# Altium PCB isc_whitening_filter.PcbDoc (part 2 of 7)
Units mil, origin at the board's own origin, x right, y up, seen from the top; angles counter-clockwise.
Board outline 8440 x 7000 mil, 6 copper layers (Top Layer, MidLayer1, InternalPlane1, Internal Plane 3, InternalPlane2, Bottom Layer); 550 components, 434 nets, 2189 pads, 806 vias.
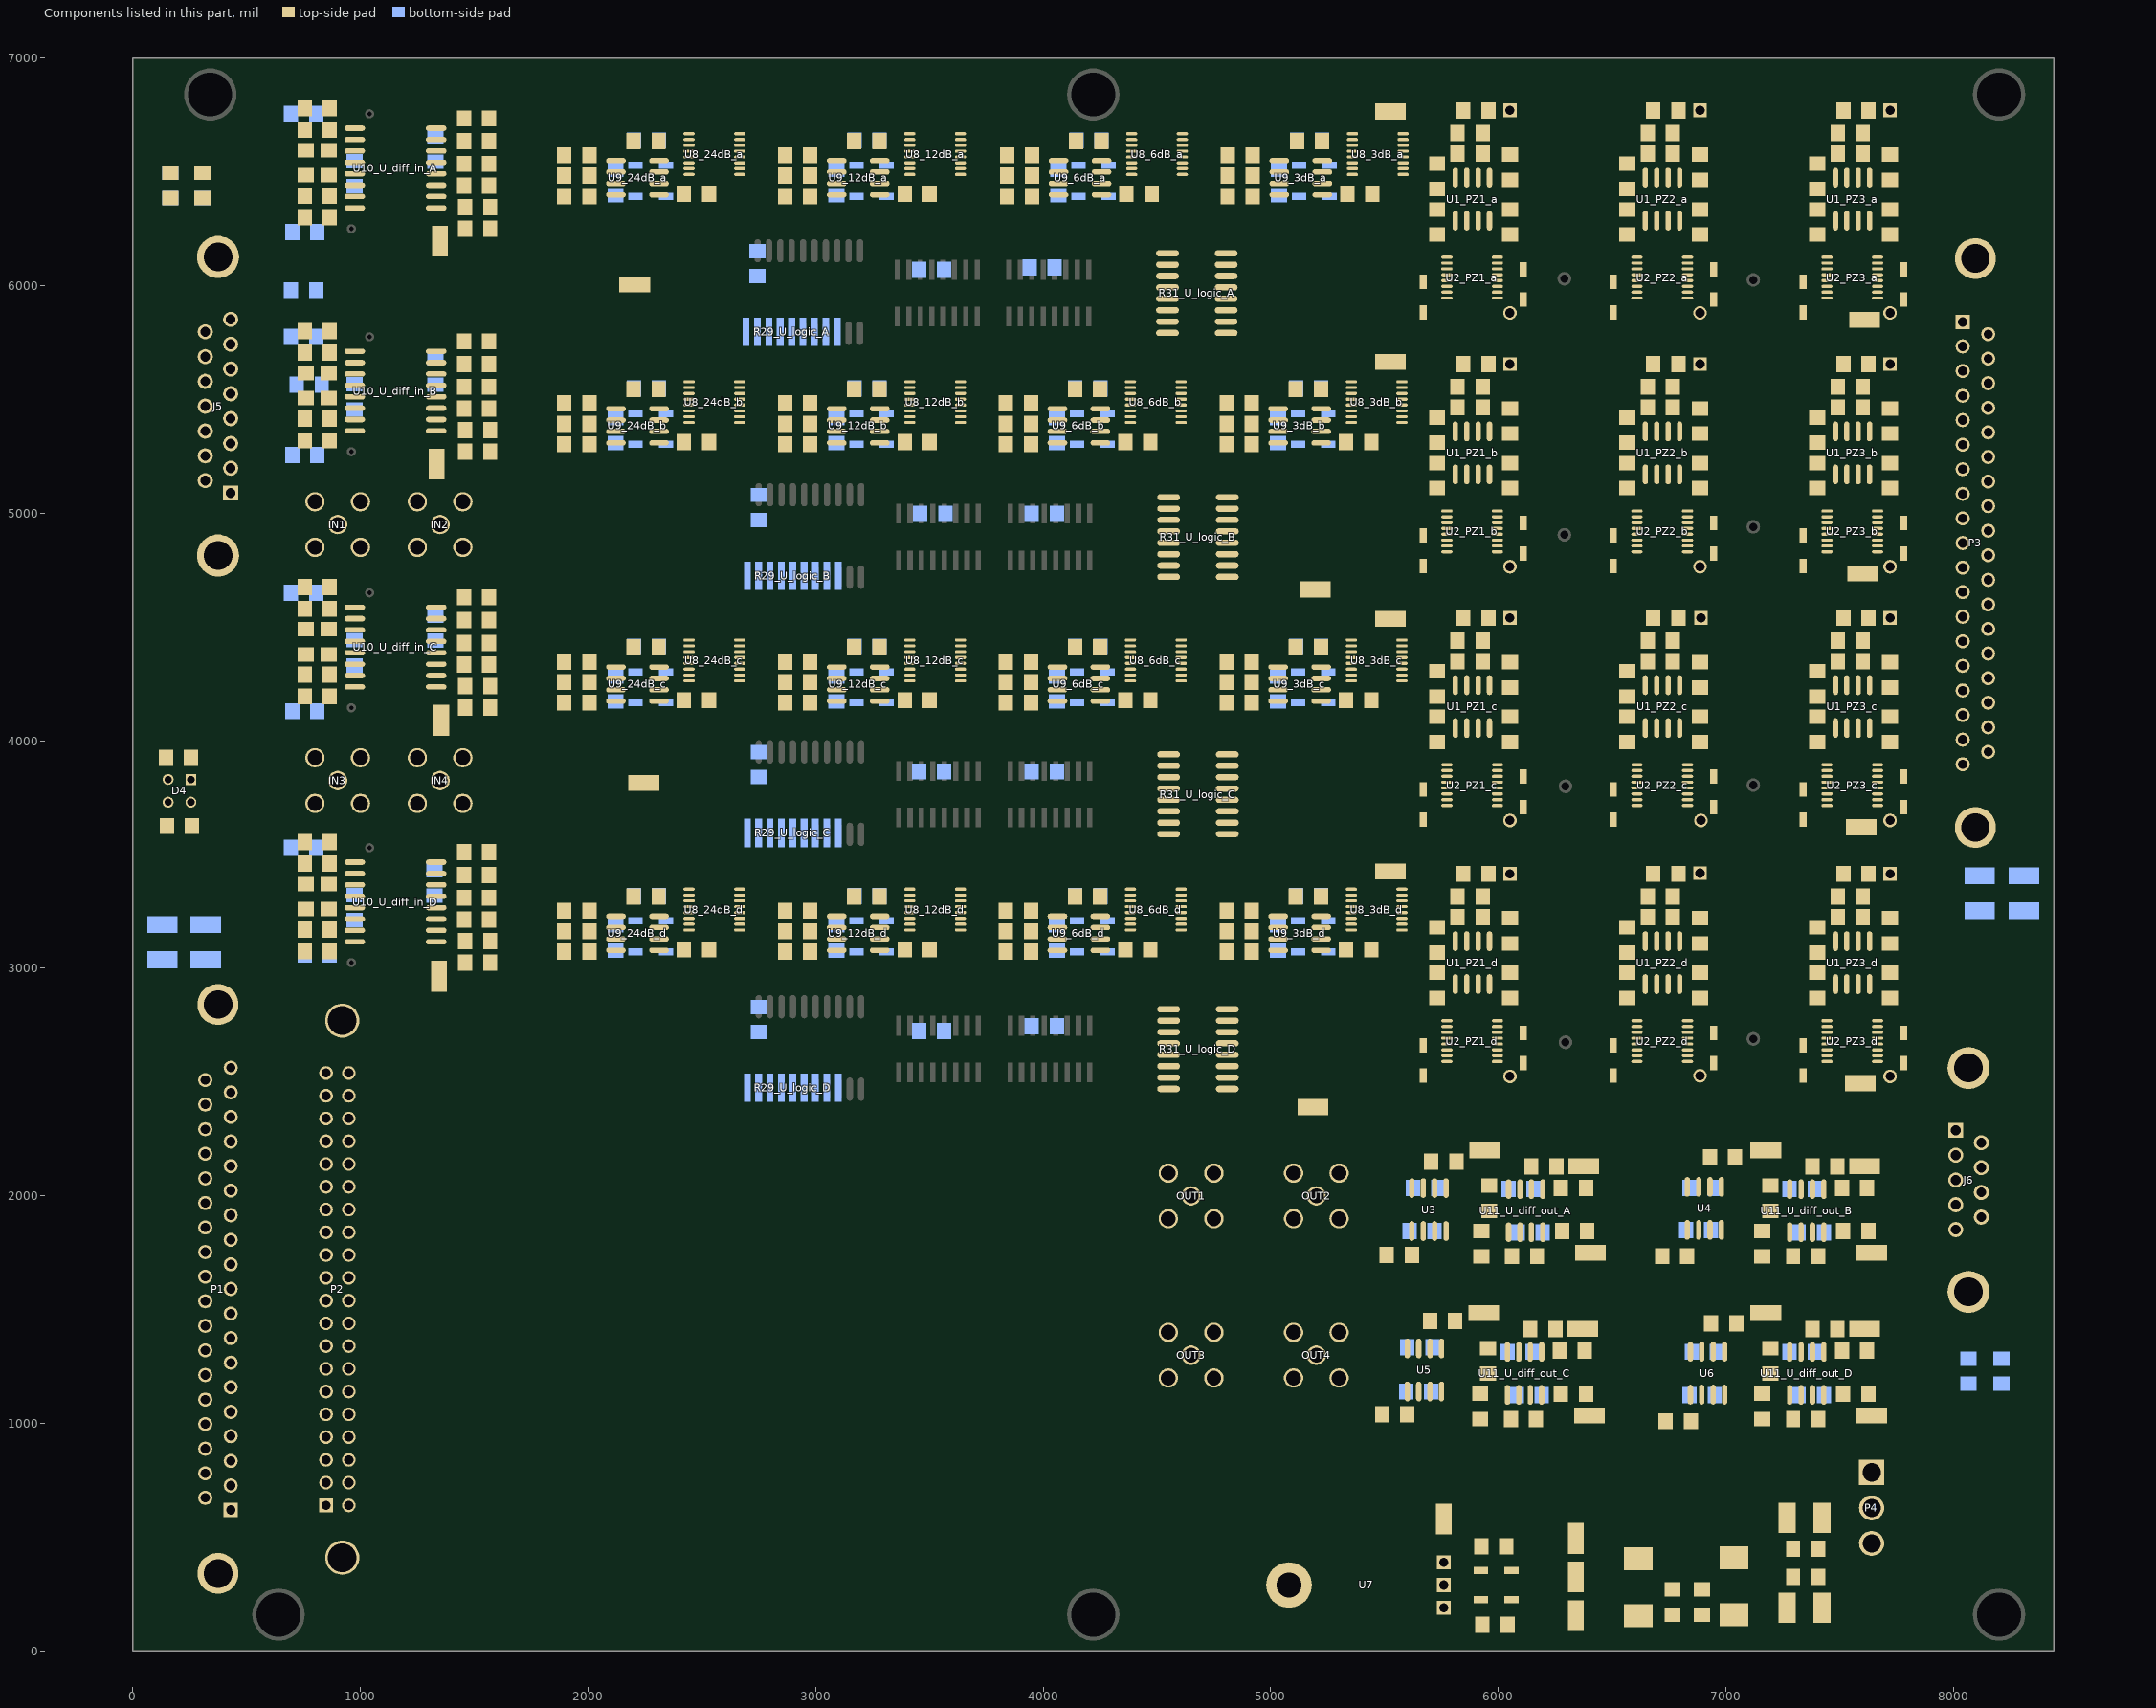
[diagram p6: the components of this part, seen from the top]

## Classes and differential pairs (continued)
component class PZ2_d: C1_PZ2_d C1_U_71 C2_PZ2_d C2_U_71 C3_PZ2_d C3_U_71 C4_PZ2_d C5_PZ2_d C5_U_71 D1_PZ2_d D1_U_71 D2_PZ2_d D2_U_71 R1_PZ2_d R2_PZ2_d R2_U_71 R3_U_71 R30_PZ2_d U1_PZ2_d U2_PZ2_d
component class PZ1_b: C1_PZ1_b C1_U_63 C2_PZ1_b C2_U_63 C3_PZ1_b C3_U_63 C4_PZ1_b C5_PZ1_b C5_U_63 D1_PZ1_b D1_U_63 D2_PZ1_b D2_U_63 R1_PZ1_b R2_PZ1_b R2_U_63 R3_U_63 R30_PZ1_b U1_PZ1_b U2_PZ1_b
component class PZ1_c: C1_PZ1_c C1_U_62 C2_PZ1_c C2_U_62 C3_PZ1_c C3_U_62 C4_PZ1_c C5_PZ1_c C5_U_62 D1_PZ1_c D1_U_62 D2_PZ1_c D2_U_62 R1_PZ1_c R2_PZ1_c R2_U_62 R3_U_62 R30_PZ1_c U1_PZ1_c U2_PZ1_c
component class PZ1_d: C1_PZ1_d C1_U_61 C2_PZ1_d C2_U_61 C3_PZ1_d C3_U_61 C4_PZ1_d C5_PZ1_d C5_U_61 D1_PZ1_d D1_U_61 D2_PZ1_d D2_U_61 R1_PZ1_d R2_PZ1_d R2_U_61 R3_U_61 R30_PZ1_d U1_PZ1_d U2_PZ1_d
component class PZ3_a: C1_PZ3_a C2_PZ3_a C3_PZ3_a C4_PZ3_a C5_PZ3_a D1_PZ3_a D2_PZ3_a R1_PZ3_a R2_PZ3_a R3_PZ3_a R30_PZ3_a U1_PZ3_a U2_PZ3_a
component class PZ2_a: C1_PZ2_a C2_PZ2_a C3_PZ2_a C4_PZ2_a C5_PZ2_a D1_PZ2_a D2_PZ2_a R1_PZ2_a R2_PZ2_a R3_PZ2_a R30_PZ2_a U1_PZ2_a U2_PZ2_a
component class PZ1_a: C1_PZ1_a C2_PZ1_a C3_PZ1_a C4_PZ1_a C5_PZ1_a D1_PZ1_a D2_PZ1_a R1_PZ1_a R2_PZ1_a R3_PZ1_a R30_PZ1_a U1_PZ1_a U2_PZ1_a
component class 24dB_d: C24_24dB_d C25_24dB_d C26_24dB_d C27_24dB_d D6_24dB_d D7_24dB_d R11_24dB_d R12_24dB_d R13_24dB_d U8_24dB_d U9_24dB_d
component class 24dB_c: C24_24dB_c C25_24dB_c C26_24dB_c C27_24dB_c D6_24dB_c D7_24dB_c R11_24dB_c R12_24dB_c R13_24dB_c U8_24dB_c U9_24dB_c
component class 24dB_b: C24_24dB_b C25_24dB_b C26_24dB_b C27_24dB_b D6_24dB_b D7_24dB_b R11_24dB_b R12_24dB_b R13_24dB_b U8_24dB_b U9_24dB_b
component class 24dB_a: C24_24dB_a C25_24dB_a C26_24dB_a C27_24dB_a D6_24dB_a D7_24dB_a R11_24dB_a R12_24dB_a R13_24dB_a U8_24dB_a U9_24dB_a
component class 12dB_d: C24_12dB_d C25_12dB_d C26_12dB_d C27_12dB_d D6_12dB_d D7_12dB_d R11_12dB_d R12_12dB_d R13_12dB_d U8_12dB_d U9_12dB_d
component class 12dB_c: C24_12dB_c C25_12dB_c C26_12dB_c C27_12dB_c D6_12dB_c D7_12dB_c R11_12dB_c R12_12dB_c R13_12dB_c U8_12dB_c U9_12dB_c
component class 12dB_b: C24_12dB_b C25_12dB_b C26_12dB_b C27_12dB_b D6_12dB_b D7_12dB_b R11_12dB_b R12_12dB_b R13_12dB_b U8_12dB_b U9_12dB_b
component class 12dB_a: C24_12dB_a C25_12dB_a C26_12dB_a C27_12dB_a D6_12dB_a D7_12dB_a R11_12dB_a R12_12dB_a R13_12dB_a U8_12dB_a U9_12dB_a
component class 6dB_d: C24_6dB_d C25_6dB_d C26_6dB_d C27_6dB_d D6_6dB_d D7_6dB_d R11_6dB_d R12_6dB_d R13_6dB_d U8_6dB_d U9_6dB_d
component class 6dB_c: C24_6dB_c C25_6dB_c C26_6dB_c C27_6dB_c D6_6dB_c D7_6dB_c R11_6dB_c R12_6dB_c R13_6dB_c U8_6dB_c U9_6dB_c
component class 6dB_b: C24_6dB_b C25_6dB_b C26_6dB_b C27_6dB_b D6_6dB_b D7_6dB_b R11_6dB_b R12_6dB_b R13_6dB_b U8_6dB_b U9_6dB_b
component class 6dB_a: C24_6dB_a C25_6dB_a C26_6dB_a C27_6dB_a D6_6dB_a D7_6dB_a R11_6dB_a R12_6dB_a R13_6dB_a U8_6dB_a U9_6dB_a
component class 3dB_d: C24_3dB_d C25_3dB_d C26_3dB_d C27_3dB_d D6_3dB_d D7_3dB_d R11_3dB_d R12_3dB_d R13_3dB_d U8_3dB_d U9_3dB_d
component class 3dB_c: C24_3dB_c C25_3dB_c C26_3dB_c C27_3dB_c D6_3dB_c D7_3dB_c R11_3dB_c R12_3dB_c R13_3dB_c U8_3dB_c U9_3dB_c
component class 3dB_b: C24_3dB_b C25_3dB_b C26_3dB_b C27_3dB_b D6_3dB_b D7_3dB_b R11_3dB_b R12_3dB_b R13_3dB_b U8_3dB_b U9_3dB_b
component class 3dB_a: C24_3dB_a C25_3dB_a C26_3dB_a C27_3dB_a D6_3dB_a D7_3dB_a R11_3dB_a R12_3dB_a R13_3dB_a U8_3dB_a U9_3dB_a
component class U_diff_in_D: C28_U_diff_in_D C29_U_diff_in_D C37_U_diff_in_D C38_U_diff_in_D C39_U_diff_in_D R14_U_diff_in_D R15_U_diff_in_D R16_U_diff_in_D R17_U_diff_in_D R18_U_diff_in_D R19_U_diff_in_D R20_U_diff_in_D R21_U_diff_in_D R22_U_diff_in_D R32_U_diff_in_D R33_U_diff_in_D U9_U_diff_in1 U10_U_diff_in_D
component class U_diff_in_C: C28_U_diff_in_C C29_U_diff_in_C C37_U_diff_in_C C38_U_diff_in_C C39_U_diff_in_C R14_U_diff_in_C R15_U_diff_in_C R16_U_diff_in_C R17_U_diff_in_C R18_U_diff_in_C R19_U_diff_in_C R20_U_diff_in_C R21_U_diff_in_C R22_U_diff_in_C R32_U_diff_in_C R33_U_diff_in_C U9_U_diff_in2 U10_U_diff_in_C
component class U_diff_in_B: C28_U_diff_in_B C29_U_diff_in_B C37_U_diff_in_B C38_U_diff_in_B C39_U_diff_in_B R14_U_diff_in_B R15_U_diff_in_B R16_U_diff_in_B R17_U_diff_in_B R18_U_diff_in_B R19_U_diff_in_B R20_U_diff_in_B R21_U_diff_in_B R22_U_diff_in_B R32_U_diff_in_B R33_U_diff_in_B U9_U_diff_in3 U10_U_diff_in_B
component class U_diff_in_A: C28_U_diff_in_A C29_U_diff_in_A C37_U_diff_in_A C38_U_diff_in_A C39_U_diff_in_A R14_U_diff_in_A R15_U_diff_in_A R16_U_diff_in_A R17_U_diff_in_A R18_U_diff_in_A R19_U_diff_in_A R20_U_diff_in_A R21_U_diff_in_A R22_U_diff_in_A R32_U_diff_in_A R33_U_diff_in_A U9_U_diff_in4 U10_U_diff_in_A
component class U_diff_out_D: C30_U_diff_out_D C31_U_diff_out_D R23_U_diff_out_D R24_U_diff_out_D R25_U_diff_out_D R26_U_diff_out_D R27_U_diff_out_D R28_U_diff_out_D TP7_U_diff_out_D TP8_U_diff_out_D TP9_U_diff_out_D U11_U_diff_out_D
component class U_diff_out_C: C30_U_diff_out_C C31_U_diff_out_C R23_U_diff_out_C R24_U_diff_out_C R25_U_diff_out_C R26_U_diff_out_C R27_U_diff_out_C R28_U_diff_out_C TP7_U_diff_out_C TP8_U_diff_out_C TP9_U_diff_out_C U11_U_diff_out_C
component class U_diff_out_B: C30_U_diff_out_B C31_U_diff_out_B R23_U_diff_out_B R24_U_diff_out_B R25_U_diff_out_B R26_U_diff_out_B R27_U_diff_out_B R28_U_diff_out_B TP7_U_diff_out_B TP8_U_diff_out_B TP9_U_diff_out_B U11_U_diff_out_B
component class U_diff_out_A: C30_U_diff_out_A C31_U_diff_out_A R23_U_diff_out_A R24_U_diff_out_A R25_U_diff_out_A R26_U_diff_out_A R27_U_diff_out_A R28_U_diff_out_A TP7_U_diff_out_A TP8_U_diff_out_A TP9_U_diff_out_A U11_U_diff_out_A
component class white_top: C6 C7 C8 C9 C10 C11 C12 C13 C14 C15 C16 C17 C18 C19 C20 C21 C22 C23 C34 C35 D3 D4 D5 D6 IN1 IN2 IN3 IN4 J5 J6 L1 L2 L5 L6 L7 L8 OUT1 OUT2 OUT3 OUT4 P1 P2 P3 P4 R3 R4 R5 R6 R7 R8 R9 R10 R34 R35 R36 R37 R38 R39 TP1 TP2 TP3 TP4 TP5 TP6 TP9 TP10 TP11 TP12 TP13 TP14 TP15 TP16 TP17 TP18 TP19 TP20 TP21 TP22 U3 U4 U5 U6 U7 U10
net class A[1..7]: A1 A2 A3 A4 A5 A6 A7
net class B[1..7]: B1 B2 B3 B4 B5 B6 B7
net class C[1..7]: C1 C2 C3 C4 C5 C6 C7
net class D[1..7]: D1 D2 D3 D4 D5 D6 D7
channel class diff_in: U_diff_in_A U_diff_in_B U_diff_in_C U_diff_in_D
channel class diff_out: U_diff_out_A U_diff_out_B U_diff_out_C U_diff_out_D
channel class filter: PZ1_a PZ1_b PZ1_c PZ1_d PZ2_a PZ2_b PZ2_c PZ2_d PZ3_a PZ3_b PZ3_c PZ3_d
channel class logic: U_logic_A U_logic_B U_logic_C U_logic_D
channel class VGA: 3dB_a 3dB_b 3dB_c 3dB_d 6dB_a 6dB_b 6dB_c 6dB_d 12dB_a 12dB_b 12dB_c 12dB_d 24dB_a 24dB_b 24dB_c 24dB_d

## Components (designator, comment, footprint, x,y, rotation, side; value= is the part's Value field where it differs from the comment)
C1_PZ1_a "100n" 3216[1206] 5731,6480 r90 top (schematic designator C1)
C1_PZ1_b "100n" 3216[1206] 5731,5365 r90 top (schematic designator C1)
C1_PZ1_c "100n" 3216[1206] 5731,4250 r90 top (schematic designator C1)
C1_PZ1_d "100n" 3216[1206] 5731,3125 r90 top (schematic designator C1)
C1_PZ2_a "100n" 3216[1206] 6566,6480 r90 top (schematic designator C1)
C1_PZ2_b "100n" 3216[1206] 6566,5365 r90 top (schematic designator C1)
C1_PZ2_c "100n" 3216[1206] 6566,4250 r90 top (schematic designator C1)
C1_PZ2_d "100n" 3216[1206] 6566,3125 r90 top (schematic designator C1)
C1_PZ3_a "100n" 3216[1206] 7401,6480 r90 top (schematic designator C1)
C1_PZ3_b "100n" 3216[1206] 7401,5365 r90 top (schematic designator C1)
C1_PZ3_c "100n" 3216[1206] 7401,4250 r90 top (schematic designator C1)
C1_PZ3_d "100n" 3216[1206] 7401,3125 r90 top (schematic designator C1)
C2_PZ1_a "68p" 3216[1206] 5731,6280 r270 top (schematic designator C2)
C2_PZ1_b "68p" 3216[1206] 5731,5165 r270 top (schematic designator C2)
C2_PZ1_c "68p" 3216[1206] 5731,4050 r270 top (schematic designator C2)
C2_PZ1_d "68p" 3216[1206] 5731,2925 r270 top (schematic designator C2)
C2_PZ2_a "68p" 3216[1206] 6566,6280 r270 top (schematic designator C2)
C2_PZ2_b "68p" 3216[1206] 6566,5165 r270 top (schematic designator C2)
C2_PZ2_c "68p" 3216[1206] 6566,4050 r270 top (schematic designator C2)
C2_PZ2_d "68p" 3216[1206] 6566,2925 r270 top (schematic designator C2)
C2_PZ3_a "68p" 3216[1206] 7401,6280 r270 top (schematic designator C2)
C2_PZ3_b "68p" 3216[1206] 7401,5165 r270 top (schematic designator C2)
C2_PZ3_c "68p" 3216[1206] 7401,4050 r270 top (schematic designator C2)
C2_PZ3_d "68p" 3216[1206] 7401,2925 r270 top (schematic designator C2)
C3_PZ1_a "100n" 3216[1206] 6051,6280 r270 top (schematic designator C3)
C3_PZ1_b "100n" 3216[1206] 6051,5165 r270 top (schematic designator C3)
C3_PZ1_c "100n" 3216[1206] 6051,4050 r270 top (schematic designator C3)
C3_PZ1_d "100n" 3216[1206] 6051,2925 r270 top (schematic designator C3)
C3_PZ2_a "100n" 3216[1206] 6886,6280 r270 top (schematic designator C3)
C3_PZ2_b "100n" 3216[1206] 6886,5165 r270 top (schematic designator C3)
C3_PZ2_c "100n" 3216[1206] 6886,4050 r270 top (schematic designator C3)
C3_PZ2_d "100n" 3216[1206] 6886,2925 r270 top (schematic designator C3)
C3_PZ3_a "100n" 3216[1206] 7721,6280 r270 top (schematic designator C3)
C3_PZ3_b "100n" 3216[1206] 7721,5165 r270 top (schematic designator C3)
C3_PZ3_c "100n" 3216[1206] 7721,4050 r270 top (schematic designator C3)
C3_PZ3_d "100n" 3216[1206] 7721,2925 r270 top (schematic designator C3)
C4_PZ1_a "100p" 3216[1206] 5876,6670 r180 top (schematic designator C4)
C4_PZ1_b "100p" 3216[1206] 5876,5555 r180 top (schematic designator C4)
C4_PZ1_c "100p" 3216[1206] 5876,4440 r180 top (schematic designator C4)
C4_PZ1_d "100p" 3216[1206] 5876,3315 r180 top (schematic designator C4)
C4_PZ2_a "100p" 3216[1206] 6711,6670 r180 top (schematic designator C4)
C4_PZ2_b "100p" 3216[1206] 6711,5555 r180 top (schematic designator C4)
C4_PZ2_c "100p" 3216[1206] 6711,4440 r180 top (schematic designator C4)
C4_PZ2_d "100p" 3216[1206] 6711,3315 r180 top (schematic designator C4)
C4_PZ3_a "100p" 3216[1206] 7546,6670 r180 top (schematic designator C4)
C4_PZ3_b "100p" 3216[1206] 7546,5555 r180 top (schematic designator C4)
C4_PZ3_c "100p" 3216[1206] 7546,4440 r180 top (schematic designator C4)
C4_PZ3_d "100p" 3216[1206] 7546,3315 r180 top (schematic designator C4)
C5_PZ1_a "10UF, Plastic" ECQ-E1106KF_Side 6051,6770 r270 bottom value="10uF, plastic" (schematic designator C5)
C5_PZ1_b "10UF, Plastic" ECQ-E1106KF_Side 6051,5655 r270 bottom value="10uF, plastic" (schematic designator C5)
C5_PZ1_c "10UF, Plastic" ECQ-E1106KF_Side 6051,4540 r270 bottom locked value="10uF, plastic" (schematic designator C5)
C5_PZ1_d "10UF, Plastic" ECQ-E1106KF_Side 6051,3415 r270 bottom locked value="10uF, plastic" (schematic designator C5)
C5_PZ2_a "10UF, Plastic" ECQ-E1106KF_Side 6886,6770 r270 bottom value="10uF, plastic" (schematic designator C5)
C5_PZ2_b "10UF, Plastic" ECQ-E1106KF_Side 6886,5655 r270 bottom value="10uF, plastic" (schematic designator C5)
C5_PZ2_c "10UF, Plastic" ECQ-E1106KF_Side 6890,4540 r270 bottom value="10uF, plastic" (schematic designator C5)
C5_PZ2_d "10UF, Plastic" ECQ-E1106KF_Side 6886,3418 r270 bottom value="10uF, plastic" (schematic designator C5)
C5_PZ3_a "10UF, Plastic" ECQ-E1106KF_Side 7721,6770 r270 bottom value="10uF, plastic" (schematic designator C5)
C5_PZ3_b "10UF, Plastic" ECQ-E1106KF_Side 7721,5655 r270 bottom value="10uF, plastic" (schematic designator C5)
C5_PZ3_c "10UF, Plastic" ECQ-E1106KF_Side 7721,4540 r270 bottom value="10uF, plastic" (schematic designator C5)
C5_PZ3_d "10UF, Plastic" ECQ-E1106KF_Side 7721,3415 r270 bottom value="10uF, plastic" (schematic designator C5)
C6 "100n" 3216[1206] 5680,2035 r180 bottom
C7 "68p" 3216[1206] 5565,1740 r0 top
C8 "100n" 3216[1206] 5665,1845 r0 bottom
C9 "100n" 3216[1206] 6895,2035 r180 bottom
C10 "68p" 3216[1206] 6775,1735 r0 top
C11 "100n" 3216[1206] 6880,1850 r0 bottom
C12 "100n" 3216[1206] 5655,1335 r180 bottom
C13 "68p" 3216[1206] 5545,1040 r0 top
C14 "100n" 3216[1206] 5650,1140 r0 bottom
C15 "100n" 3216[1206] 6905,1315 r180 bottom
C16 "68p" 3216[1206] 6790,1010 r0 top
C17 "100n" 3216[1206] 6895,1125 r0 bottom
C18 "10UF Tantalum, 35V" 7343-31 7035,410 r90 top value=10uF
C19 "100n" 3216[1206] 6895,215 r270 top
C20 "1u" 3216[1206] 5985,115 r180 top
C21 "1u" 3216[1206] 5980,460 r180 top
C22 "100n" 3216[1206] 6765,215 r90 top
C23 "10UF Tantalum, 35V" 7343-31 6615,405 r90 top value=10uF
C24_3dB_a "100n" 3216[1206] 5036,6453 r270 bottom (schematic designator C24)
C24_3dB_b "100n" 3216[1206] 5031,5363 r270 bottom (schematic designator C24)
C24_3dB_c "100n" 3216[1206] 5031,4228 r270 bottom (schematic designator C24)
C24_3dB_d "100n" 3216[1206] 5031,3133 r270 bottom (schematic designator C24)
C24_6dB_a "100n" 3216[1206] 4066,6453 r270 bottom (schematic designator C24)
C24_6dB_b "100n" 3216[1206] 4061,5363 r270 bottom (schematic designator C24)
C24_6dB_c "100n" 3216[1206] 4061,4228 r270 bottom (schematic designator C24)
C24_6dB_d "100n" 3216[1206] 4061,3133 r270 bottom (schematic designator C24)
C24_12dB_a "100n" 3216[1206] 3091,6453 r270 bottom (schematic designator C24)
C24_12dB_b "100n" 3216[1206] 3091,5363 r270 bottom (schematic designator C24)
C24_12dB_c "100n" 3216[1206] 3091,4228 r270 bottom (schematic designator C24)
C24_12dB_d "100n" 3216[1206] 3091,3133 r270 bottom (schematic designator C24)
C24_24dB_a "100n" 3216[1206] 2121,6453 r270 bottom (schematic designator C24)
C24_24dB_b "100n" 3216[1206] 2121,5363 r270 bottom (schematic designator C24)
C24_24dB_c "100n" 3216[1206] 2121,4228 r270 bottom (schematic designator C24)
C24_24dB_d "100n" 3216[1206] 2121,3133 r270 bottom (schematic designator C24)
C25_3dB_a "68p" 3216[1206] 5391,6403 r180 top (schematic designator C25)
C25_3dB_b "68p" 3216[1206] 5386,5313 r180 top (schematic designator C25)
C25_3dB_c "68p" 3216[1206] 5386,4178 r180 top (schematic designator C25)
C25_3dB_d "68p" 3216[1206] 5386,3083 r180 top (schematic designator C25)
C25_6dB_a "68p" 3216[1206] 4421,6403 r180 top (schematic designator C25)
C25_6dB_b "68p" 3216[1206] 4416,5313 r180 top (schematic designator C25)
C25_6dB_c "68p" 3216[1206] 4416,4178 r180 top (schematic designator C25)
C25_6dB_d "68p" 3216[1206] 4416,3083 r180 top (schematic designator C25)
C25_12dB_a "68p" 3216[1206] 3446,6403 r180 top (schematic designator C25)
C25_12dB_b "68p" 3216[1206] 3446,5313 r180 top (schematic designator C25)
C25_12dB_c "68p" 3216[1206] 3446,4178 r180 top (schematic designator C25)
C25_12dB_d "68p" 3216[1206] 3446,3083 r180 top (schematic designator C25)
C25_24dB_a "68p" 3216[1206] 2476,6403 r180 top (schematic designator C25)
C25_24dB_b "68p" 3216[1206] 2476,5313 r180 top (schematic designator C25)
C25_24dB_c "68p" 3216[1206] 2476,4178 r180 top (schematic designator C25)
C25_24dB_d "68p" 3216[1206] 2476,3083 r180 top (schematic designator C25)
C26_3dB_a "100n" 3216[1206] 5171,6638 r0 bottom (schematic designator C26)
C26_3dB_b "100n" 3216[1206] 5166,5548 r0 bottom (schematic designator C26)
C26_3dB_c "100n" 3216[1206] 5166,4413 r0 bottom (schematic designator C26)
C26_3dB_d "100n" 3216[1206] 5166,3318 r0 bottom (schematic designator C26)
C26_6dB_a "100n" 3216[1206] 4201,6638 r0 bottom (schematic designator C26)
C26_6dB_b "100n" 3216[1206] 4196,5548 r0 bottom (schematic designator C26)
C26_6dB_c "100n" 3216[1206] 4196,4413 r0 bottom (schematic designator C26)
C26_6dB_d "100n" 3216[1206] 4196,3318 r0 bottom (schematic designator C26)
C26_12dB_a "100n" 3216[1206] 3226,6638 r0 bottom (schematic designator C26)
C26_12dB_b "100n" 3216[1206] 3226,5548 r0 bottom (schematic designator C26)
C26_12dB_c "100n" 3216[1206] 3226,4413 r0 bottom (schematic designator C26)
C26_12dB_d "100n" 3216[1206] 3226,3318 r0 bottom (schematic designator C26)
C26_24dB_a "100n" 3216[1206] 2256,6638 r0 bottom (schematic designator C26)
C26_24dB_b "100n" 3216[1206] 2256,5548 r0 bottom (schematic designator C26)
C26_24dB_c "100n" 3216[1206] 2256,4413 r0 bottom (schematic designator C26)
C26_24dB_d "100n" 3216[1206] 2256,3318 r0 bottom (schematic designator C26)
C27_3dB_a "33pF" 3216[1206] 4866,6573 r0 top (schematic designator C27)
C27_3dB_b "33pF" 3216[1206] 4861,5483 r0 top (schematic designator C27)
C27_3dB_c "33pF" 3216[1206] 4861,4348 r0 top (schematic designator C27)
C27_3dB_d "33pF" 3216[1206] 4861,3253 r0 top (schematic designator C27)
C27_6dB_a "20pf" 3216[1206] 3896,6573 r0 top value=20pF (schematic designator C27)
C27_6dB_b "20pf" 3216[1206] 3891,5483 r0 top value=20pF (schematic designator C27)
C27_6dB_c "20pf" 3216[1206] 3891,4348 r0 top value=20pF (schematic designator C27)
C27_6dB_d "20pf" 3216[1206] 3891,3253 r0 top value=20pF (schematic designator C27)
C27_12dB_a "10pf" 3216[1206] 2921,6573 r0 top value=10pF (schematic designator C27)
C27_12dB_b "10pf" 3216[1206] 2921,5483 r0 top value=10pF (schematic designator C27)
C27_12dB_c "10pf" 3216[1206] 2921,4348 r0 top value=10pF (schematic designator C27)
C27_12dB_d "10pf" 3216[1206] 2921,3253 r0 top value=10pF (schematic designator C27)
C27_24dB_a "5.6pf" 3216[1206] 1951,6573 r0 top value=5.6pF (schematic designator C27)
C27_24dB_b "5.6pf" 3216[1206] 1951,5483 r0 top value=5.6pF (schematic designator C27)
C27_24dB_c "5.6pf" 3216[1206] 1951,4348 r0 top value=5.6pF (schematic designator C27)
C27_24dB_d "5.6pf" 3216[1206] 1951,3253 r0 top value=5.6pF (schematic designator C27)
C28_U_diff_in_A "1u" 3216[1206] 974.53,6491.5 r270 bottom (schematic designator C28)
C28_U_diff_in_B "1u" 3216[1206] 974.53,5511.5 r270 bottom (schematic designator C28)
C28_U_diff_in_C "1u" 3216[1206] 974.53,4386.5 r270 bottom (schematic designator C28)
C28_U_diff_in_D "1u" 3216[1206] 974.53,3266.5 r270 bottom (schematic designator C28)
C29_U_diff_in_A "1u" 3216[1206] 1330,6600 r90 bottom (schematic designator C29)
C29_U_diff_in_B "1u" 3216[1206] 1330,5620 r90 bottom (schematic designator C29)
C29_U_diff_in_C "1u" 3216[1206] 1330,4495 r90 bottom (schematic designator C29)
C29_U_diff_in_D "1u" 3216[1206] 1325,3375 r90 bottom (schematic designator C29)
C30_U_diff_out_A "100n" 3216[1206] 6140,1840 r180 bottom (schematic designator C30)
C30_U_diff_out_B "100n" 3216[1206] 7375,1840 r180 bottom (schematic designator C30)
C30_U_diff_out_C "100n" 3216[1206] 6135,1125 r180 bottom (schematic designator C30)
C30_U_diff_out_D "100n" 3216[1206] 7375,1125 r180 bottom (schematic designator C30)
C31_U_diff_out_A "100n" 3216[1206] 6100,2030 r0 bottom (schematic designator C31)
C31_U_diff_out_B "100n" 3216[1206] 7335,2030 r0 bottom (schematic designator C31)
C31_U_diff_out_C "100n" 3216[1206] 6095,1315 r0 bottom (schematic designator C31)
C31_U_diff_out_D "100n" 3216[1206] 7335,1315 r0 bottom (schematic designator C31)
C32_U_logic_A "100n" 3216[1206] 3510,6070 r0 bottom (schematic designator C32)
C32_U_logic_B "100n" 3216[1206] 3515,4997.36 r0 bottom (schematic designator C32)
C32_U_logic_C "100n" 3216[1206] 3510,3865 r0 bottom (schematic designator C32)
C32_U_logic_D "100n" 3216[1206] 3510,2725 r0 bottom (schematic designator C32)
C33_U_logic_A "100n" 3216[1206] 2745,6097 r90 bottom (schematic designator C33)
C33_U_logic_B "100n" 3216[1206] 2750,5025 r90 bottom (schematic designator C33)
C33_U_logic_C "100n" 3216[1206] 2750,3895 r90 bottom (schematic designator C33)
C33_U_logic_D "100n" 3216[1206] 2750,2775 r90 bottom (schematic designator C33)
C34 "1u" 3216[1206] 165,6440 r270 bottom
C35 "1u" 3216[1206] 8065,1230 r90 bottom
C36_U_logic_A "100n" 3216[1206] 3995,6080 r0 bottom (schematic designator C36)
C36_U_logic_B "100n" 3216[1206] 4005,4997.36 r0 bottom (schematic designator C36)
C36_U_logic_C "100n" 3216[1206] 4005,3865 r0 bottom (schematic designator C36)
C36_U_logic_D "100n" 3216[1206] 4005,2745 r0 bottom (schematic designator C36)
C37_U_diff_in_A "5.6n" 3216[1206] 1510,6735 r180 top (schematic designator C37)
C37_U_diff_in_B "5.6n" 3216[1206] 1510,5755 r180 top (schematic designator C37)
C37_U_diff_in_C "5.6n" 3216[1206] 1510,4630 r180 top (schematic designator C37)
C37_U_diff_in_D "5.6n" 3216[1206] 1510,3510 r180 top (schematic designator C37)
C38_U_diff_in_A "5.6n" 3216[1206] 860,6540 r270 top (schematic designator C38)
C38_U_diff_in_B "5.6n" 3216[1206] 860,5560 r270 top (schematic designator C38)
C38_U_diff_in_C "5.6n" 3216[1206] 860,4435 r270 top (schematic designator C38)
C38_U_diff_in_D "5.6n" 3216[1206] 860,3315 r270 top (schematic designator C38)
C39_U_diff_in_A "5.6n" 3216[1206] 1515,6250 r0 top (schematic designator C39)
C39_U_diff_in_B "5.6n" 3216[1206] 1515,5270 r0 top (schematic designator C39)
C39_U_diff_in_C "5.6n" 3216[1206] 1515,4145 r0 top (schematic designator C39)
C39_U_diff_in_D "5.6n" 3216[1206] 1515,3025 r0 top (schematic designator C39)
D1_PZ1_a "60V, 1A Schottky" sod123 5670,5950 r270 top value="Diode 1 Amp" (schematic designator D1)
D1_PZ1_b "60V, 1A Schottky" sod123 5670,4835 r270 top value="Diode 1 Amp" (schematic designator D1)
D1_PZ1_c "60V, 1A Schottky" sod123 5670,3720 r270 top value="Diode 1 Amp" (schematic designator D1)
D1_PZ1_d "60V, 1A Schottky" sod123 5670,2595 r270 top value="Diode 1 Amp" (schematic designator D1)
D1_PZ2_a "60V, 1A Schottky" sod123 6505,5950 r270 top value="Diode 1 Amp" (schematic designator D1)
D1_PZ2_b "60V, 1A Schottky" sod123 6505,4835 r270 top value="Diode 1 Amp" (schematic designator D1)
D1_PZ2_c "60V, 1A Schottky" sod123 6505,3720 r270 top value="Diode 1 Amp" (schematic designator D1)
D1_PZ2_d "60V, 1A Schottky" sod123 6505,2595 r270 top value="Diode 1 Amp" (schematic designator D1)
D1_PZ3_a "60V, 1A Schottky" sod123 7340,5950 r270 top value="Diode 1 Amp" (schematic designator D1)
D1_PZ3_b "60V, 1A Schottky" sod123 7340,4835 r270 top value="Diode 1 Amp" (schematic designator D1)
D1_PZ3_c "60V, 1A Schottky" sod123 7340,3720 r270 top value="Diode 1 Amp" (schematic designator D1)
D1_PZ3_d "60V, 1A Schottky" sod123 7340,2595 r270 top value="Diode 1 Amp" (schematic designator D1)
D2_PZ1_a "60V, 1A Schottky" sod123 6110,6005 r90 top value="Diode 1 Amp" (schematic designator D2)
D2_PZ1_b "60V, 1A Schottky" sod123 6110,4890 r90 top value="Diode 1 Amp" (schematic designator D2)
D2_PZ1_c "60V, 1A Schottky" sod123 6110,3775 r90 top value="Diode 1 Amp" (schematic designator D2)
D2_PZ1_d "60V, 1A Schottky" sod123 6110,2650 r90 top value="Diode 1 Amp" (schematic designator D2)
D2_PZ2_a "60V, 1A Schottky" sod123 6945,6005 r90 top value="Diode 1 Amp" (schematic designator D2)
D2_PZ2_b "60V, 1A Schottky" sod123 6945,4890 r90 top value="Diode 1 Amp" (schematic designator D2)
D2_PZ2_c "60V, 1A Schottky" sod123 6945,3775 r90 top value="Diode 1 Amp" (schematic designator D2)
D2_PZ2_d "60V, 1A Schottky" sod123 6945,2650 r90 top value="Diode 1 Amp" (schematic designator D2)
D2_PZ3_a "60V, 1A Schottky" sod123 7780,6005 r90 top value="Diode 1 Amp" (schematic designator D2)
D2_PZ3_b "60V, 1A Schottky" sod123 7780,4890 r90 top value="Diode 1 Amp" (schematic designator D2)
D2_PZ3_c "60V, 1A Schottky" sod123 7780,3775 r90 top value="Diode 1 Amp" (schematic designator D2)
D2_PZ3_d "60V, 1A Schottky" sod123 7780,2650 r90 top value="Diode 1 Amp" (schematic designator D2)
D3 "60V, 1A Schottky" sod123 5990,355 r0 top value="Diode 1 Amp"
D4 "Stacked LED" "my LUMEX Dual LED" 255,3830 r0 top locked
D5 "60V, 1A Schottky" sod123 5990,225 r0 top value="Diode 1 Amp"
D6_3dB_a "60V, 1A Schottky" sod123 5191,6393 r180 bottom value="Diode 1 Amp" (schematic designator D6)
D6_3dB_b "60V, 1A Schottky" sod123 5186,5303 r180 bottom value="Diode 1 Amp" (schematic designator D6)
D6_3dB_c "60V, 1A Schottky" sod123 5186,4168 r180 bottom value="Diode 1 Amp" (schematic designator D6)
D6_3dB_d "60V, 1A Schottky" sod123 5186,3073 r180 bottom value="Diode 1 Amp" (schematic designator D6)
D6_6dB_a "60V, 1A Schottky" sod123 4221,6393 r180 bottom value="Diode 1 Amp" (schematic designator D6)
D6_6dB_b "60V, 1A Schottky" sod123 4216,5303 r180 bottom value="Diode 1 Amp" (schematic designator D6)
D6_6dB_c "60V, 1A Schottky" sod123 4216,4168 r180 bottom value="Diode 1 Amp" (schematic designator D6)
D6_6dB_d "60V, 1A Schottky" sod123 4216,3073 r180 bottom value="Diode 1 Amp" (schematic designator D6)
D6_12dB_a "60V, 1A Schottky" sod123 3246,6393 r180 bottom value="Diode 1 Amp" (schematic designator D6)
D6_12dB_b "60V, 1A Schottky" sod123 3246,5303 r180 bottom value="Diode 1 Amp" (schematic designator D6)
D6_12dB_c "60V, 1A Schottky" sod123 3246,4168 r180 bottom value="Diode 1 Amp" (schematic designator D6)
D6_12dB_d "60V, 1A Schottky" sod123 3246,3073 r180 bottom value="Diode 1 Amp" (schematic designator D6)
D6_24dB_a "60V, 1A Schottky" sod123 2276,6393 r180 bottom value="Diode 1 Amp" (schematic designator D6)
D6_24dB_b "60V, 1A Schottky" sod123 2276,5303 r180 bottom value="Diode 1 Amp" (schematic designator D6)
D6_24dB_c "60V, 1A Schottky" sod123 2276,4168 r180 bottom value="Diode 1 Amp" (schematic designator D6)
D6_24dB_d "60V, 1A Schottky" sod123 2276,3073 r180 bottom value="Diode 1 Amp" (schematic designator D6)
D7_3dB_a "60V, 1A Schottky" sod123 5191,6528 r180 bottom value="Diode 1 Amp" (schematic designator D7)
D7_3dB_b "60V, 1A Schottky" sod123 5186,5438 r180 bottom value="Diode 1 Amp" (schematic designator D7)
D7_3dB_c "60V, 1A Schottky" sod123 5186,4303 r180 bottom value="Diode 1 Amp" (schematic designator D7)
D7_3dB_d "60V, 1A Schottky" sod123 5186,3208 r180 bottom value="Diode 1 Amp" (schematic designator D7)
D7_6dB_a "60V, 1A Schottky" sod123 4221,6528 r180 bottom value="Diode 1 Amp" (schematic designator D7)
D7_6dB_b "60V, 1A Schottky" sod123 4216,5438 r180 bottom value="Diode 1 Amp" (schematic designator D7)
D7_6dB_c "60V, 1A Schottky" sod123 4216,4303 r180 bottom value="Diode 1 Amp" (schematic designator D7)
D7_6dB_d "60V, 1A Schottky" sod123 4216,3208 r180 bottom value="Diode 1 Amp" (schematic designator D7)
D7_12dB_a "60V, 1A Schottky" sod123 3246,6528 r180 bottom value="Diode 1 Amp" (schematic designator D7)
D7_12dB_b "60V, 1A Schottky" sod123 3246,5438 r180 bottom value="Diode 1 Amp" (schematic designator D7)
D7_12dB_c "60V, 1A Schottky" sod123 3246,4303 r180 bottom value="Diode 1 Amp" (schematic designator D7)
D7_12dB_d "60V, 1A Schottky" sod123 3246,3208 r180 bottom value="Diode 1 Amp" (schematic designator D7)
D7_24dB_a "60V, 1A Schottky" sod123 2276,6528 r180 bottom value="Diode 1 Amp" (schematic designator D7)
D7_24dB_b "60V, 1A Schottky" sod123 2276,5438 r180 bottom value="Diode 1 Amp" (schematic designator D7)
D7_24dB_c "60V, 1A Schottky" sod123 2276,4303 r180 bottom value="Diode 1 Amp" (schematic designator D7)
D7_24dB_d "60V, 1A Schottky" sod123 2276,3208 r180 bottom value="Diode 1 Amp" (schematic designator D7)
IN1 "SMA" SMA 900,4950 r270 top
IN2 "SMA" SMA 1350,4950 r270 top
IN3 "SMA" SMA 900,3825 r270 top
IN4 "SMA" SMA 1350,3825 r270 top
J5 "D Connector 15" DSUB1.385-2H15 0,5470 r90 top locked value="15 pin connector Receptacle"
J6 "D Connector 9" DSUB1.385-2H9 8440,2070 r270 top value="9 pin connector Receptacle"
L1 "NL" 1812 7345,585 r180 top
L2 "NL" 1812 7345,190 r180 top
L5 "10UH, 360mA" 1812 130,3115 r90 bottom value="10uH, 360mA"
L6 "10UH, 360mA" 1812 320,3115 r90 bottom value="10uH, 360mA"
L7 "10UH, 360mA" 1812 8310,3330 r270 bottom value="10uH, 360mA"
L8 "10UH, 360mA" 1812 8115,3330 r270 bottom value="10uH, 360mA"
OUT1 "SMA" SMA 4650,2000 r90 top
OUT2 "SMA" SMA 5200,2000 r90 top
OUT3 "SMA" SMA 4650,1300 r90 top
OUT4 "SMA" SMA 5200,1300 r90 top
P1 "37 pin connector" DB37/F/RA/125MT 430,620 r90 top locked value="37 pin connector Receptacle"
P2 "Header 20X2H" MY_40-pin_Header_RA 920,410 r90 bottom
P3 "37 pin connector" DB37/F/RA/125MT 8040,5840 r270 top value="37 pin connector Receptacle"
P4 "Header 3H" Molex_156_RA_3 7640,785 r0 top
R1_PZ1_a "15K" 3216[1206] 5876,6580 r0 top (schematic designator R1)
R1_PZ1_b "15K" 3216[1206] 5876,5465 r0 top (schematic designator R1)
R1_PZ1_c "15K" 3216[1206] 5876,4350 r0 top (schematic designator R1)
R1_PZ1_d "15K" 3216[1206] 5876,3225 r0 top (schematic designator R1)
R1_PZ2_a "15K" 3216[1206] 6711,6580 r0 top (schematic designator R1)
R1_PZ2_b "15K" 3216[1206] 6711,5465 r0 top (schematic designator R1)
R1_PZ2_c "15K" 3216[1206] 6711,4350 r0 top (schematic designator R1)
R1_PZ2_d "15K" 3216[1206] 6711,3225 r0 top (schematic designator R1)
R1_PZ3_a "15K" 3216[1206] 7546,6580 r0 top (schematic designator R1)
R1_PZ3_b "15K" 3216[1206] 7546,5465 r0 top (schematic designator R1)
R1_PZ3_c "15K" 3216[1206] 7546,4350 r0 top (schematic designator R1)
R1_PZ3_d "15K" 3216[1206] 7546,3225 r0 top (schematic designator R1)
R2_PZ1_a "1.58k" 3216[1206] 5901,6770 r180 top (schematic designator R2)
R2_PZ1_b "1.58k" 3216[1206] 5901,5655 r180 top (schematic designator R2)
R2_PZ1_c "1.58k" 3216[1206] 5901,4540 r180 top (schematic designator R2)
R2_PZ1_d "1.58k" 3216[1206] 5901,3415 r180 top (schematic designator R2)
R2_PZ2_a "1.58k" 3216[1206] 6736,6770 r180 top (schematic designator R2)
R2_PZ2_b "1.58k" 3216[1206] 6736,5655 r180 top (schematic designator R2)
R2_PZ2_c "1.58k" 3216[1206] 6736,4540 r180 top (schematic designator R2)
R2_PZ2_d "1.58k" 3216[1206] 6736,3415 r180 top (schematic designator R2)
R2_PZ3_a "1.58k" 3216[1206] 7571,6770 r180 top (schematic designator R2)
R2_PZ3_b "1.58k" 3216[1206] 7571,5655 r180 top (schematic designator R2)
R2_PZ3_c "1.58k" 3216[1206] 7571,4540 r180 top (schematic designator R2)
R2_PZ3_d "1.58k" 3216[1206] 7571,3415 r180 top (schematic designator R2)
R3 "0" 3216[1206] 5760,2150 r0 top
R4 "0" 3216[1206] 6985,2170 r0 top
R5 "0" 3216[1206] 5755,1450 r0 top
R6 "0" 3216[1206] 6990,1440 r0 top
R7 "1K" 3216[1206] 305,6440 r90 top
R8 "1K" 3216[1206] 165,6440 r90 top
R9 "1K" 3216[1206] 205,3625 r0 top
R10 "1K" 3216[1206] 200,3925 r180 top
R11_3dB_a "15K" 3216[1206] 5170,6635 r180 top (schematic designator R11)
R11_3dB_b "15K" 3216[1206] 5165,5545 r180 top (schematic designator R11)
R11_3dB_c "15K" 3216[1206] 5165,4410 r180 top (schematic designator R11)
R11_3dB_d "15K" 3216[1206] 5165,3315 r180 top (schematic designator R11)
R11_6dB_a "15K" 3216[1206] 4200,6635 r180 top (schematic designator R11)
R11_6dB_b "15K" 3216[1206] 4195,5545 r180 top (schematic designator R11)
R11_6dB_c "15K" 3216[1206] 4195,4410 r180 top (schematic designator R11)
R11_6dB_d "15K" 3216[1206] 4195,3315 r180 top (schematic designator R11)
R11_12dB_a "15K" 3216[1206] 3225,6635 r180 top (schematic designator R11)
R11_12dB_b "15K" 3216[1206] 3225,5545 r180 top (schematic designator R11)
R11_12dB_c "15K" 3216[1206] 3225,4410 r180 top (schematic designator R11)
R11_12dB_d "15K" 3216[1206] 3225,3315 r180 top (schematic designator R11)
R11_24dB_a "15K" 3216[1206] 2255,6635 r180 top (schematic designator R11)
R11_24dB_b "15K" 3216[1206] 2255,5545 r180 top (schematic designator R11)
R11_24dB_c "15K" 3216[1206] 2255,4410 r180 top (schematic designator R11)
R11_24dB_d "15K" 3216[1206] 2255,3315 r180 top (schematic designator R11)
R12_3dB_a "1.65K" 3216[1206] 4866,6393 r0 top (schematic designator R12)
R12_3dB_b "1.65K" 3216[1206] 4861,5303 r0 top (schematic designator R12)
R12_3dB_c "1.65K" 3216[1206] 4861,4168 r0 top (schematic designator R12)
R12_3dB_d "1.65K" 3216[1206] 4861,3073 r0 top (schematic designator R12)
R12_6dB_a "1K" 3216[1206] 3896,6393 r0 top (schematic designator R12)
R12_6dB_b "1K" 3216[1206] 3891,5303 r0 top (schematic designator R12)
R12_6dB_c "1K" 3216[1206] 3891,4168 r0 top (schematic designator R12)
R12_6dB_d "1K" 3216[1206] 3891,3073 r0 top (schematic designator R12)
R12_12dB_a "549" 3216[1206] 2921,6393 r0 top (schematic designator R12)
R12_12dB_b "549" 3216[1206] 2921,5303 r0 top (schematic designator R12)
R12_12dB_c "549" 3216[1206] 2921,4168 r0 top (schematic designator R12)
R12_12dB_d "549" 3216[1206] 2921,3073 r0 top (schematic designator R12)
R12_24dB_a "200" 3216[1206] 1951,6393 r0 top (schematic designator R12)
R12_24dB_b "200" 3216[1206] 1951,5303 r0 top (schematic designator R12)
R12_24dB_c "200" 3216[1206] 1951,4168 r0 top (schematic designator R12)
R12_24dB_d "200" 3216[1206] 1951,3073 r0 top (schematic designator R12)
R13_3dB_a "680" 3216[1206] 4866,6483 r180 top (schematic designator R13)
R13_3dB_b "680" 3216[1206] 4861,5393 r180 top (schematic designator R13)
R13_3dB_c "680" 3216[1206] 4861,4258 r180 top (schematic designator R13)
R13_3dB_d "680" 3216[1206] 4861,3163 r180 top (schematic designator R13)
R13_6dB_a "1K" 3216[1206] 3896,6483 r180 top (schematic designator R13)
R13_6dB_b "1K" 3216[1206] 3891,5393 r180 top (schematic designator R13)
R13_6dB_c "1K" 3216[1206] 3891,4258 r180 top (schematic designator R13)
R13_6dB_d "1K" 3216[1206] 3891,3163 r180 top (schematic designator R13)
R13_12dB_a "1.65K" 3216[1206] 2921,6483 r180 top (schematic designator R13)
R13_12dB_b "1.65K" 3216[1206] 2921,5393 r180 top (schematic designator R13)
R13_12dB_c "1.65K" 3216[1206] 2921,4258 r180 top (schematic designator R13)
R13_12dB_d "1.65K" 3216[1206] 2921,3163 r180 top (schematic designator R13)
R13_24dB_a "3K" 3216[1206] 1951,6483 r180 top (schematic designator R13)
R13_24dB_b "3K" 3216[1206] 1951,5393 r180 top (schematic designator R13)
R13_24dB_c "3K" 3216[1206] 1951,4258 r180 top (schematic designator R13)
R13_24dB_d "3K" 3216[1206] 1951,3163 r180 top (schematic designator R13)
R14_U_diff_in_A "1M" 3216[1206] 755,6235 r180 bottom (schematic designator R14)
R14_U_diff_in_B "1M" 3216[1206] 755,5255 r180 bottom (schematic designator R14)
R14_U_diff_in_C "1M" 3216[1206] 755,4130 r180 bottom (schematic designator R14)
R14_U_diff_in_D "1M" 3216[1206] 810,3060 r180 bottom (schematic designator R14)
R15_U_diff_in_A "3K" 3216[1206] 1510,6535 r0 top (schematic designator R15)
R15_U_diff_in_B "3K" 3216[1206] 1510,5555 r0 top (schematic designator R15)
R15_U_diff_in_C "3K" 3216[1206] 1510,4430 r0 top (schematic designator R15)
R15_U_diff_in_D "3K" 3216[1206] 1510,3310 r0 top (schematic designator R15)
R16_U_diff_in_A "1.5K" 3216[1206] 1510,6635 r0 top (schematic designator R16)
R16_U_diff_in_B "1.5K" 3216[1206] 1510,5655 r0 top (schematic designator R16)
R16_U_diff_in_C "1.5K" 3216[1206] 1510,4530 r0 top (schematic designator R16)
R16_U_diff_in_D "1.5K" 3216[1206] 1510,3410 r0 top (schematic designator R16)
R17_U_diff_in_A "0" 3216[1206] 810,6300 r180 top (schematic designator R17)
R17_U_diff_in_B "0" 3216[1206] 810,5320 r180 top (schematic designator R17)
R17_U_diff_in_C "0" 3216[1206] 810,4195 r180 top (schematic designator R17)
R17_U_diff_in_D "0" 3216[1206] 810,3075 r180 top (schematic designator R17)
R18_U_diff_in_A "NL" 3216[1206] 760,6540 r270 top (schematic designator R18)
R18_U_diff_in_B "NL" 3216[1206] 760,5560 r270 top (schematic designator R18)
R18_U_diff_in_C "NL" 3216[1206] 760,4435 r270 top (schematic designator R18)
R18_U_diff_in_D "NL" 3216[1206] 760,3315 r270 top (schematic designator R18)
R19_U_diff_in_A "0" 3216[1206] 810,6780 r180 top (schematic designator R19)
R19_U_diff_in_B "0" 3216[1206] 810,5800 r180 top (schematic designator R19)
R19_U_diff_in_C "0" 3216[1206] 810,4675 r180 top (schematic designator R19)
R19_U_diff_in_D "0" 3216[1206] 810,3555 r180 top (schematic designator R19)
R20_U_diff_in_A "1.5K" 3216[1206] 1515,6345 r180 top (schematic designator R20)
R20_U_diff_in_B "1.5K" 3216[1206] 1515,5365 r180 top (schematic designator R20)
R20_U_diff_in_C "1.5K" 3216[1206] 1515,4240 r180 top (schematic designator R20)
R20_U_diff_in_D "1.5K" 3216[1206] 1515,3120 r180 top (schematic designator R20)
R21_U_diff_in_A "3K" 3216[1206] 1510,6440 r0 top (schematic designator R21)
R21_U_diff_in_B "3K" 3216[1206] 1510,5460 r0 top (schematic designator R21)
R21_U_diff_in_C "3K" 3216[1206] 1510,4335 r0 top (schematic designator R21)
R21_U_diff_in_D "3K" 3216[1206] 1510,3215 r0 top (schematic designator R21)
R22_U_diff_in_A "1M" 3216[1206] 750,6755 r0 bottom (schematic designator R22)
R22_U_diff_in_B "1M" 3216[1206] 750,5775 r0 bottom (schematic designator R22)
R22_U_diff_in_C "1M" 3216[1206] 750,4650 r0 bottom (schematic designator R22)
R22_U_diff_in_D "1M" 3216[1206] 750,3530 r0 bottom (schematic designator R22)
R23_U_diff_out_A "0" 3216[1206] 6330,2035 r0 top (schematic designator R23)
R23_U_diff_out_B "0" 3216[1206] 7565,2035 r0 top (schematic designator R23)
R23_U_diff_out_C "0" 3216[1206] 6325,1320 r0 top (schematic designator R23)
R23_U_diff_out_D "0" 3216[1206] 7565,1320 r0 top (schematic designator R23)
R24_U_diff_out_A "4.99K" 3216[1206] 5960,1990 r90 top (schematic designator R24)
R24_U_diff_out_B "4.99K" 3216[1206] 7195,1990 r90 top (schematic designator R24)
R24_U_diff_out_C "4.99K" 3216[1206] 5955,1275 r90 top (schematic designator R24)
R24_U_diff_out_D "4.99K" 3216[1206] 7195,1275 r90 top (schematic designator R24)
R25_U_diff_out_A "4.99K" 3216[1206] 6200,2130 r0 top (schematic designator R25)
R25_U_diff_out_B "4.99K" 3216[1206] 7435,2130 r0 top (schematic designator R25)
R25_U_diff_out_C "4.99K" 3216[1206] 6195,1415 r0 top (schematic designator R25)
R25_U_diff_out_D "4.99K" 3216[1206] 7435,1415 r0 top (schematic designator R25)
R26_U_diff_out_A "0" 3216[1206] 6335,1845 r0 top (schematic designator R26)
R26_U_diff_out_B "0" 3216[1206] 7570,1845 r0 top (schematic designator R26)
R26_U_diff_out_C "0" 3216[1206] 6330,1130 r0 top (schematic designator R26)
R26_U_diff_out_D "0" 3216[1206] 7570,1130 r0 top (schematic designator R26)
R27_U_diff_out_A "4.99K" 3216[1206] 5925,1790 r270 top (schematic designator R27)
R27_U_diff_out_B "4.99K" 3216[1206] 7160,1790 r270 top (schematic designator R27)
R27_U_diff_out_C "4.99K" 3216[1206] 5920,1075 r270 top (schematic designator R27)
R27_U_diff_out_D "4.99K" 3216[1206] 7160,1075 r270 top (schematic designator R27)
R28_U_diff_out_A "4.99K" 3216[1206] 6115,1735 r0 top (schematic designator R28)
R28_U_diff_out_B "4.99K" 3216[1206] 7350,1735 r0 top (schematic designator R28)
R28_U_diff_out_C "4.99K" 3216[1206] 6110,1020 r0 top (schematic designator R28)
R28_U_diff_out_D "4.99K" 3216[1206] 7350,1020 r0 top (schematic designator R28)
R29_U_logic_A "10K" SRT9 2694.41,5797 r270 bottom (schematic designator R29)
R29_U_logic_B "10K" SRT9 2699.41,4725 r270 bottom (schematic designator R29)
R29_U_logic_C "10K" SRT9 2699.41,3595 r270 bottom (schematic designator R29)
R29_U_logic_D "10K" SRT9 2699.41,2475 r270 bottom (schematic designator R29)
R30_PZ1_a "15K" 3216[1206] 6051,6520 r90 top (schematic designator R30)
R30_PZ1_b "15K" 3216[1206] 6051,5405 r90 top (schematic designator R30)
R30_PZ1_c "15K" 3216[1206] 6051,4290 r90 top (schematic designator R30)
R30_PZ1_d "15K" 3216[1206] 6051,3165 r90 top (schematic designator R30)
R30_PZ2_a "15K" 3216[1206] 6886,6520 r90 top (schematic designator R30)
R30_PZ2_b "15K" 3216[1206] 6886,5405 r90 top (schematic designator R30)
R30_PZ2_c "15K" 3216[1206] 6886,4290 r90 top (schematic designator R30)
R30_PZ2_d "15K" 3216[1206] 6886,3165 r90 top (schematic designator R30)
R30_PZ3_a "15K" 3216[1206] 7721,6520 r90 top (schematic designator R30)
R30_PZ3_b "15K" 3216[1206] 7721,5405 r90 top (schematic designator R30)
R30_PZ3_c "15K" 3216[1206] 7721,4290 r90 top (schematic designator R30)
R30_PZ3_d "15K" 3216[1206] 7721,3165 r90 top (schematic designator R30)
R31_U_logic_A "560" SOP127P760X300-16M 4675,5967 r0 top (schematic designator R31)
R31_U_logic_B "560" SOP127P760X300-16M 4680,4895 r0 top (schematic designator R31)
R31_U_logic_C "560" SOP127P760X300-16M 4680,3765 r0 top (schematic designator R31)
R31_U_logic_D "560" SOP127P760X300-16M 4680,2645 r0 top (schematic designator R31)
R32_U_diff_in_A "1K" 3216[1206] 810,6395 r180 top (schematic designator R32)
R32_U_diff_in_B "1K" 3216[1206] 810,5415 r180 top (schematic designator R32)
R32_U_diff_in_C "1K" 3216[1206] 810,4290 r180 top (schematic designator R32)
R32_U_diff_in_D "1K" 3216[1206] 810,3170 r180 top (schematic designator R32)
R33_U_diff_in_A "1K" 3216[1206] 810,6685 r180 top (schematic designator R33)
R33_U_diff_in_B "1K" 3216[1206] 810,5705 r180 top (schematic designator R33)
R33_U_diff_in_C "1K" 3216[1206] 810,4580 r180 top (schematic designator R33)
R33_U_diff_in_D "1K" 3216[1206] 810,3460 r180 top (schematic designator R33)
R34 "49.9" 3216[1206] 305,6440 r270 bottom
R35 "0" 3216[1206] 775,5565 r0 bottom
R36 "0" 3216[1206] 750,5980 r180 bottom
R37 "49.9" 3216[1206] 8210,1230 r90 bottom
R38 "0" 3216[1206] 7350,450 r180 top
R39 "0" 3216[1206] 7350,325 r180 top
TP1 "TEST POINT" TP_SMT_MICRO 1350,6195 r90 top
TP2 "TEST POINT" TP_SMT_MICRO 5525,6765 r180 top
TP3 "TEST POINT" TP_SMT_MICRO 6340,495 r270 top
TP4 "TEST POINT" TP_SMT_MICRO 6340,325 r270 top
TP5 "TEST POINT" TP_SMT_MICRO 5760,580 r270 top
TP6 "TEST POINT" TP_SMT_MICRO 6340,155 r270 top
TP7_U_diff_out_A "TEST POINT" TP_SMT_MICRO 6375,2130 r180 top (schematic designator TP7)
TP7_U_diff_out_B "TEST POINT" TP_SMT_MICRO 7610,2130 r180 top (schematic designator TP7)
TP7_U_diff_out_C "TEST POINT" TP_SMT_MICRO 6370,1415 r180 top (schematic designator TP7)
TP7_U_diff_out_D "TEST POINT" TP_SMT_MICRO 7610,1415 r180 top (schematic designator TP7)
TP8_U_diff_out_A "TEST POINT" TP_SMT_MICRO 5940,2200 r0 top (schematic designator TP8)
TP8_U_diff_out_B "TEST POINT" TP_SMT_MICRO 7175,2200 r0 top (schematic designator TP8)
TP8_U_diff_out_C "TEST POINT" TP_SMT_MICRO 5935,1485 r0 top (schematic designator TP8)
TP8_U_diff_out_D "TEST POINT" TP_SMT_MICRO 7175,1485 r0 top (schematic designator TP8)
TP9 "TEST POINT" TP_SMT_MICRO 2205,6005 r180 top
TP9_U_diff_out_A "TEST POINT" TP_SMT_MICRO 6405,1750 r0 top (schematic designator TP9)
TP9_U_diff_out_B "TEST POINT" TP_SMT_MICRO 7640,1750 r0 top (schematic designator TP9)
TP9_U_diff_out_C "TEST POINT" TP_SMT_MICRO 6400,1035 r0 top (schematic designator TP9)
TP9_U_diff_out_D "TEST POINT" TP_SMT_MICRO 7640,1035 r0 top (schematic designator TP9)
TP10 "TEST POINT" TP_SMT_MICRO 5195,4665 r0 top
TP11 "TEST POINT" TP_SMT_MICRO 2245,3815 r180 top
TP12 "TEST POINT" TP_SMT_MICRO 5185,2390 r180 top
TP13 "TEST POINT" TP_SMT_MICRO 7610,5850 r180 top
TP14 "TEST POINT" TP_SMT_MICRO 1335,5215 r270 top
TP15 "TEST POINT" TP_SMT_MICRO 5525,5665 r0 top
TP16 "TEST POINT" TP_SMT_MICRO 7600,4735 r0 top
TP17 "TEST POINT" TP_SMT_MICRO 1355,4090 r270 top
TP18 "TEST POINT" TP_SMT_MICRO 5525,4535 r0 top
TP19 "TEST POINT" TP_SMT_MICRO 7595,3620 r180 top
TP20 "TEST POINT" TP_SMT_MICRO 1345,2965 r270 top
TP21 "TEST POINT" TP_SMT_MICRO 5525,3425 r0 top
TP22 "TEST POINT" TP_SMT_MICRO 7590,2495 r180 top
U1_PZ1_a "OP27GS" SOIC127P600-8N 5886,6380 r270 top (schematic designator U1)
U1_PZ1_b "OP27GS" SOIC127P600-8N 5886,5265 r270 top (schematic designator U1)
U1_PZ1_c "OP27GS" SOIC127P600-8N 5886,4150 r270 top (schematic designator U1)
U1_PZ1_d "OP27GS" SOIC127P600-8N 5886,3025 r270 top (schematic designator U1)
U1_PZ2_a "OP27GS" SOIC127P600-8N 6721,6380 r270 top (schematic designator U1)
U1_PZ2_b "OP27GS" SOIC127P600-8N 6721,5265 r270 top (schematic designator U1)
U1_PZ2_c "OP27GS" SOIC127P600-8N 6721,4150 r270 top (schematic designator U1)
U1_PZ2_d "OP27GS" SOIC127P600-8N 6721,3025 r270 top (schematic designator U1)
U1_PZ3_a "OP27GS" SOIC127P600-8N 7556,6380 r270 top (schematic designator U1)
U1_PZ3_b "OP27GS" SOIC127P600-8N 7556,5265 r270 top (schematic designator U1)
U1_PZ3_c "OP27GS" SOIC127P600-8N 7556,4150 r270 top (schematic designator U1)
U1_PZ3_d "OP27GS" SOIC127P600-8N 7556,3025 r270 top (schematic designator U1)
U2_PZ1_a "ADG1436YRUZ-REEL7" ADI-RU-16_L 5885,6035 r0 top (schematic designator U2)
U2_PZ1_b "ADG1436YRUZ-REEL7" ADI-RU-16_L 5885,4920 r0 top (schematic designator U2)
U2_PZ1_c "ADG1436YRUZ-REEL7" ADI-RU-16_L 5885,3805 r0 top (schematic designator U2)
U2_PZ1_d "ADG1436YRUZ-REEL7" ADI-RU-16_L 5885,2680 r0 top (schematic designator U2)
U2_PZ2_a "ADG1436YRUZ-REEL7" ADI-RU-16_L 6720,6035 r0 top (schematic designator U2)
U2_PZ2_b "ADG1436YRUZ-REEL7" ADI-RU-16_L 6720,4920 r0 top (schematic designator U2)
U2_PZ2_c "ADG1436YRUZ-REEL7" ADI-RU-16_L 6720,3805 r0 top (schematic designator U2)
U2_PZ2_d "ADG1436YRUZ-REEL7" ADI-RU-16_L 6720,2680 r0 top (schematic designator U2)
U2_PZ3_a "ADG1436YRUZ-REEL7" ADI-RU-16_L 7555,6035 r0 top (schematic designator U2)
U2_PZ3_b "ADG1436YRUZ-REEL7" ADI-RU-16_L 7555,4920 r0 top (schematic designator U2)
U2_PZ3_c "ADG1436YRUZ-REEL7" ADI-RU-16_L 7555,3805 r0 top (schematic designator U2)
U2_PZ3_d "ADG1436YRUZ-REEL7" ADI-RU-16_L 7555,2680 r0 top (schematic designator U2)
U3 "OP27GS" SOIC127P600-8N 5695,1940 r270 top
U4 "OP27GS" SOIC127P600-8N 6905,1945 r270 top
U5 "OP27GS" SOIC127P600-8N 5675,1235 r270 top
U6 "OP27GS" SOIC127P600-8N 6919,1221 r270 top
U7 "MC7805CT" MY_TO220 5760,290 r90 top
U8_3dB_a "ADG1436YRUZ-REEL7" ADI-RU-16_L 5470,6577.8 r180 top (schematic designator U8)
U8_3dB_b "ADG1436YRUZ-REEL7" ADI-RU-16_L 5465,5487.8 r180 top (schematic designator U8)
U8_3dB_c "ADG1436YRUZ-REEL7" ADI-RU-16_L 5465,4352.8 r180 top (schematic designator U8)
U8_3dB_d "ADG1436YRUZ-REEL7" ADI-RU-16_L 5465,3257.8 r180 top (schematic designator U8)
U8_6dB_a "ADG1436YRUZ-REEL7" ADI-RU-16_L 4500,6577.8 r180 top (schematic designator U8)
